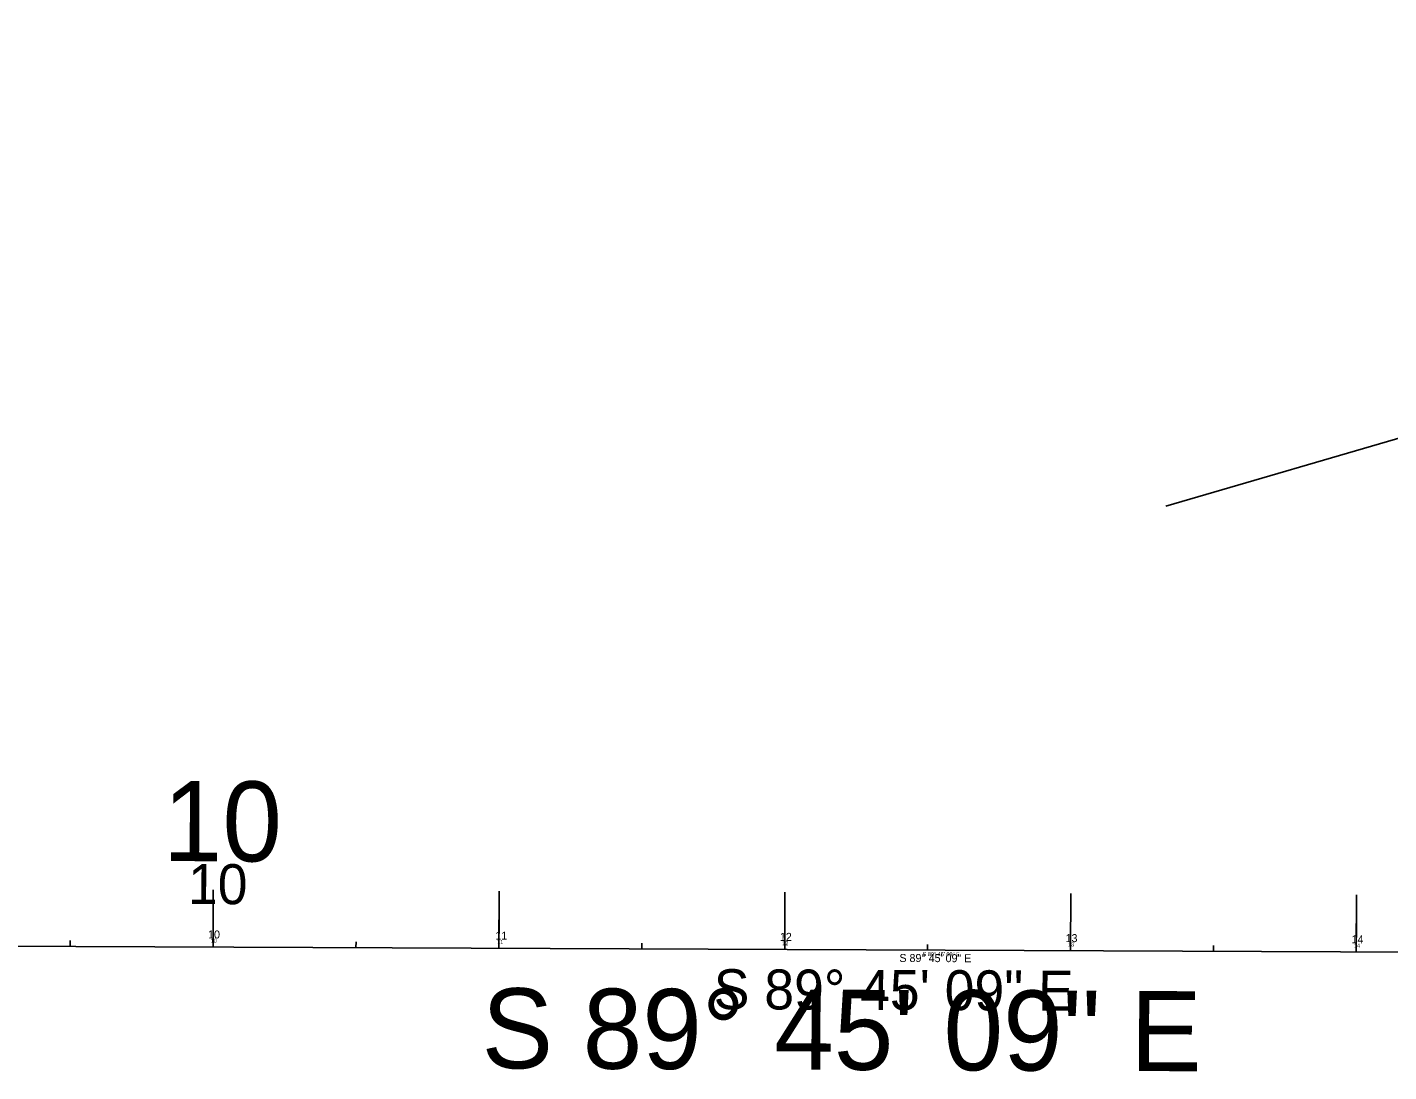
# Model space of a CAD drawing. Extents: x 1794716 to 1797874, y 325521 to 329174.
# Drawn here: x 1795192.2 to 1795668.6, y 327485.2 to 327850.7 of the extents above; entities that cross this region are included whole.
import ezdxf

# ---------------------------------------------------------------- set-up
doc = ezdxf.new("R2010")
doc.units = 0
for name, color, linetype in [('GE_P_CL_10', 7, 'Continuous'), ('GE_P_CL_100', 7, 'Continuous'), ('GE_P_CL_20', 7, 'Continuous'), ('GE_P_CL_200', 7, 'Continuous'), ('GE_X_CL_30', 7, 'Continuous'), ('RW_X_CL_20', 7, 'Continuous')]:
    doc.layers.add(name, color=color, linetype=linetype)

msp = doc.modelspace()

# ---------------------------------------------------------------- linework, layer by layer
at = {"layer": 'GE_P_CL_10'}
for p, q in [((1794757.21, 327531.04), (1796269.93, 327524.51)), ((1795207.21, 327529.1), (1795207.21, 327530.1)), ((1795257.21, 327528.88), (1795257.21, 327529.88)), ((1795307.21, 327528.67), (1795307.21, 327529.67)), ((1795357.21, 327528.45), (1795357.21, 327529.45)), ((1795407.21, 327528.24), (1795407.21, 327529.24)), ((1795457.21, 327528.02), (1795457.21, 327529.02)), ((1795507.21, 327527.8), (1795507.21, 327528.8)), ((1795557.21, 327527.59), (1795557.21, 327528.59)), ((1795607.2, 327527.37), (1795607.21, 327528.37)), ((1795657.2, 327527.16), (1795657.21, 327528.16))]:
    msp.add_line(p, q, dxfattribs=at)
at = {"layer": 'GE_P_CL_100'}
for p, q in [((1795257.21, 327528.88), (1795257.25, 327538.88)), ((1795357.21, 327528.45), (1795357.25, 327538.45)), ((1795457.21, 327528.02), (1795457.25, 327538.02)), ((1795557.21, 327527.59), (1795557.25, 327537.59)), ((1795657.2, 327527.16), (1795657.25, 327537.16)), ((1794757.21, 327531.04), (1796269.93, 327524.51))]:
    msp.add_line(p, q, dxfattribs=at)
at = {"layer": 'GE_P_CL_20'}
for p, q in [((1794757.21, 327531.04), (1796269.93, 327524.51)), ((1795207.21, 327529.1), (1795207.22, 327531.1)), ((1795257.21, 327528.88), (1795257.22, 327530.88)), ((1795307.21, 327528.67), (1795307.22, 327530.67)), ((1795357.21, 327528.45), (1795357.22, 327530.45)), ((1795407.21, 327528.24), (1795407.22, 327530.24)), ((1795457.21, 327528.02), (1795457.21, 327530.02)), ((1795507.21, 327527.8), (1795507.21, 327529.8)), ((1795557.21, 327527.59), (1795557.21, 327529.59)), ((1795607.2, 327527.37), (1795607.21, 327529.37)), ((1795657.2, 327527.16), (1795657.21, 327529.16))]:
    msp.add_line(p, q, dxfattribs=at)
at = {"layer": 'GE_P_CL_200'}
for p, q in [((1796164.22, 327850.67), (1795590.52, 327683.06)), ((1795257.21, 327528.88), (1795257.29, 327548.88)), ((1795357.21, 327528.45), (1795357.29, 327548.45)), ((1795457.21, 327528.02), (1795457.29, 327548.02)), ((1795557.21, 327527.59), (1795557.29, 327547.59)), ((1795657.2, 327527.16), (1795657.29, 327547.16)), ((1794757.21, 327531.04), (1796269.93, 327524.51))]:
    msp.add_line(p, q, dxfattribs=at)
at = {"layer": 'GE_X_CL_30'}
msp.add_line((1794757.21, 327531.04), (1796269.93, 327524.51), dxfattribs=at)
at = {"layer": 'RW_X_CL_20'}
msp.add_line((1794757.21, 327531.04), (1796269.93, 327524.51), dxfattribs=at)

# ---------------------------------------------------------------- texts
at = {"layer": 'GE_P_CL_10'}
for s, p in [('10', (1795256.33, 327530.39)), ('11', (1795356.59, 327529.95)), ('12', (1795456.36, 327529.52)), ('13', (1795556.34, 327529.09)), ('14', (1795656.36, 327528.66)), ('S 89%%d 45\' 09" E', (1795505.45, 327525.71))]:
    msp.add_text(s, height=1.4, rotation=359.7526, dxfattribs=at).set_placement(p)
at = {"layer": 'GE_P_CL_100'}
for s, p in [('10', (1795248.4, 327543.92)), ('S 89%%d 45\' 09" E', (1795432.36, 327507.13))]:
    msp.add_text(s, height=14, rotation=359.7526, dxfattribs=at).set_placement(p)
at = {"layer": 'GE_P_CL_20'}
for s, p in [('10', (1795255.45, 327531.89)), ('11', (1795355.98, 327531.46)), ('12', (1795455.51, 327531.03)), ('13', (1795555.48, 327530.6)), ('14', (1795655.52, 327530.16)), ('S 89%%d 45\' 09" E', (1795497.33, 327523.65))]:
    msp.add_text(s, height=2.8, rotation=359.7526, dxfattribs=at).set_placement(p)
at = {"layer": 'GE_P_CL_200'}
for s, p in [('10', (1795239.6, 327558.96)), ('S 89%%d 45\' 09" E', (1795351.14, 327486.48))]:
    msp.add_text(s, height=28, rotation=359.7526, dxfattribs=at).set_placement(p)

doc.saveas('drawing.dxf')
